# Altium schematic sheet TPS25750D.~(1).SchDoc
size A2; Date: Not shown in title block; ApprovedBy: Not shown in title block; CheckedBy: Not shown in title block; Author: Not shown in title block; CompanyName: Not shown in title block; Engineer: Not shown in title block; Organization: Not shown in title block; Address1: Not shown in title block; Address2: Not shown in title block; Address3: Not shown in title block; Address4: Not shown in title block; DocumentNumber: 2; Revision: Use project parameter SCH_Rev; SheetNumber: 2; SheetTotal: 3; PageSetup: Record=PageOptions¦CenterHorizontal=True¦CenterVertical=True¦PrintScale=1.00¦XCorrection=1.00¦YCorrection=1.00¦PrintKind=0¦BorderSize=5000000¦LeftOffset=0¦BottomOffset=0¦Orientation=2¦PaperLength=1000¦PaperWidth=1000¦Scale=100¦PaperSource=15¦PrintQuality=600¦MediaType=1¦DitherType=10¦PaperKind=Letter¦PrintScaleMode=1
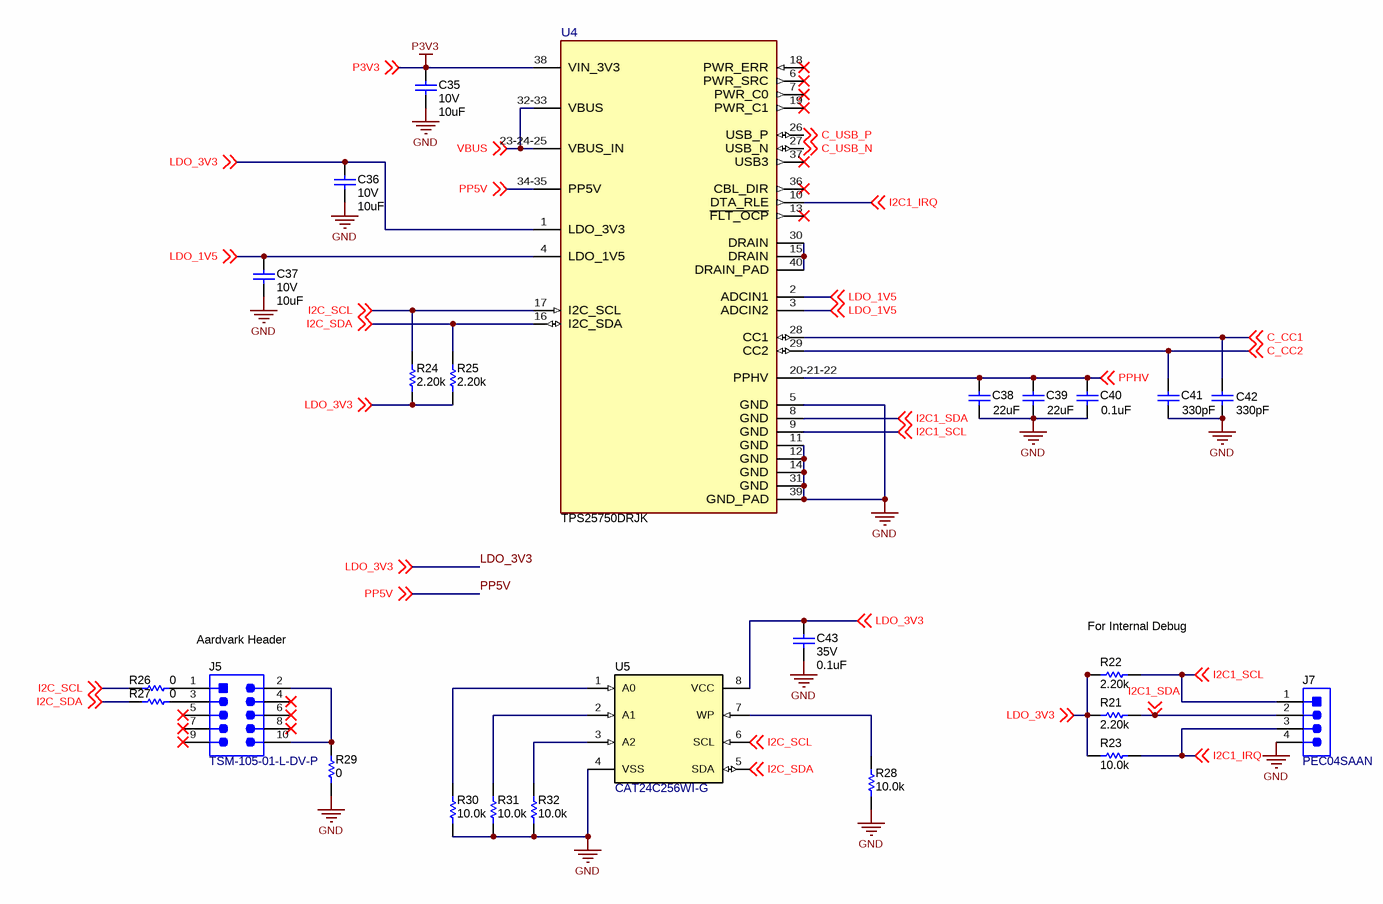
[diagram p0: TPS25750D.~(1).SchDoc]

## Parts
C35  VDC_V: 10V  ValueDisplayed: 10uF  [0402_070]  (hidden comment: CL05A106MP5NUNC)
C36  VDC_V: 10V  ValueDisplayed: 10uF  [0402_070]  (hidden comment: CL05A106MP5NUNC)
C37  VDC_V: 10V  ValueDisplayed: 10uF  [0402_070]  (hidden comment: CL05A106MP5NUNC)
C38  ValueDisplayed: 22uF  [0805_HV]  (hidden comment: C2012X5R1V226M125AC)
C39  ValueDisplayed: 22uF  [0805_HV]  (hidden comment: C2012X5R1V226M125AC)
C40  ValueDisplayed: 0.1uF  [0402]  (hidden comment: GMK105BJ104KV-F)
C41  ValueDisplayed: 330pF  [0201_033]  (hidden comment: GRM033R71H331KA12D)
C42  ValueDisplayed: 330pF  [0201_033]  (hidden comment: GRM033R71H331KA12D)
C43  VDC_V: 35V  ValueDisplayed: 0.1uF  [0402]  (hidden comment: GMK105BJ104KV-F)
J5  TSM-105-01-L-DV-P  [Samtec_TSM-105-01-x-DV]
J7  PEC04SAAN  [SULLINS_PEC04SAAN]
R21  ValueDisplayed: 2.20k  [0201]  (hidden comment: CRCW02012K20FKED)
R22  ValueDisplayed: 2.20k  [0201]  (hidden comment: CRCW02012K20FKED)
R23  ValueDisplayed: 10.0k  [0201]  (hidden comment: CRCW020110K0FKED)
R24  ValueDisplayed: 2.20k  [0201]  (hidden comment: CRCW02012K20FKED)
R25  ValueDisplayed: 2.20k  [0201]  (hidden comment: CRCW02012K20FKED)
R26  ValueDisplayed: 0  [0201]  (hidden comment: CRCW02010000Z0ED)
R27  ValueDisplayed: 0  [0201]  (hidden comment: CRCW02010000Z0ED)
R28  ValueDisplayed: 10.0k  [0201]  (hidden comment: CRCW020110K0FKED)
R29  ValueDisplayed: 0  [0201]  (hidden comment: CRCW02010000Z0ED)
R30  ValueDisplayed: 10.0k  [0201]  (hidden comment: CRCW020110K0FKED)
R31  ValueDisplayed: 10.0k  [0201]  (hidden comment: CRCW020110K0FKED)
R32  ValueDisplayed: 10.0k  [0201]  (hidden comment: CRCW020110K0FKED)
U4  TPS25750DRJK  [RJK0038B-C01-MFG]
U5  CAT24C256WI-G  [SOIC-8]

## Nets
GND: C35.2 C36.2 C37.2 C38.2 C39.2 C40.2 C41.2 C42.2 C43.2 J7.4 R28.1 R29.1 R30.1 R31.1 R32.1 U4.5(GND) U4.11(GND) U4.12(GND) U4.14(GND) U4.31(GND) U4.39(GND_PAD) U5.4(VSS)
P3V3: C35.1 U4.38(VIN_3V3) ; off-sheet P3V3
C_CC1: C42.1 U4.28(CC1) ; off-sheet C_CC1
C_CC2: C41.1 U4.29(CC2) ; off-sheet C_CC2
C_USB_N: U4.27(USB_N) ; off-sheet C_USB_N
C_USB_P: U4.26(USB_P) ; off-sheet C_USB_P
I2C1_IRQ: J7.3 R23.1 U4.10(DTA_RLE) ; off-sheet I2C1_IRQ
I2C1_SCL: J7.1 R22.1 U4.9(GND) ; off-sheet I2C1_SCL
I2C1_SDA: J7.2 R21.1 U4.8(GND) ; off-sheet I2C1_SDA
I2C_SCL: R24.2 R26.1 U4.17(I2C_SCL) U5.6(SCL) ; off-sheet I2C_SCL
I2C_SDA: R25.2 R27.1 U4.16(I2C_SDA) U5.5(SDA) ; off-sheet I2C_SDA
LDO_1V5: C37.1 U4.2(ADCIN1) U4.3(ADCIN2) U4.4(LDO_1V5) ; off-sheet LDO_1V5
LDO_3V3: C36.1 C43.1 R21.2 R22.2 R23.2 R24.1 R25.1 U4.1(LDO_3V3) U5.8(VCC) ; off-sheet LDO_3V3
PP5V: U4.34-35(PP5V) ; off-sheet PP5V
PPHV: C38.1 C39.1 C40.1 U4.20-21-22(PPHV) ; off-sheet PPHV
VBUS: U4.23-24-25(VBUS_IN) U4.32-33(VBUS) ; off-sheet VBUS
NetJ5_1: J5.1 R26.2
NetJ5_2: J5.2 J5.10 R29.2
NetJ5_3: J5.3 R27.2
NetR28_2: R28.2 U5.7(WP)
NetR30_2: R30.2 U5.1(A0)
NetR31_2: R31.2 U5.2(A1)
NetR32_2: R32.2 U5.3(A2)
NetU4_15: U4.15(DRAIN) U4.30(DRAIN) U4.40(DRAIN_PAD)

Not connected (* = marked no-connect by the designer): J5 4* 5* 6* 7* 8* 9*; U4 6(PWR_SRC)* 7(PWR_C0)* 13(~{FLT_OCP})* 18(PWR_ERR)* 19(PWR_C1)* 36(CBL_DIR)* 37(USB3)*

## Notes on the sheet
- Aardvark Header
- (near R22) For Internal Debug

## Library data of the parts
C35-C37 = CMP-0006339-4: CAP, CERM, 10 uF, 10 V, +/- 20%, X5R, 0402; Manufacturer: Samsung Electro-Mechanics; TaMin_C: -55°C; Polarized: N; SizeAreaWB_mm2: 3; Value1: Unknown; U/M: EA; Value: 10uF; TaMax_C: 85°C; SizeZ_mm: 0.6; SizeX_mm: 1; SizeY_mm: 0.5; Cap_Case: 0402; Cap_F: 10µF; AEC Category: Q200
C38 C39 = CMP-0007844-2: CAP, CERM, 22 uF, 35 V, +/- 20%, X5R, 0805; Manufacturer: TDK; TaMin_C: -55°C; ESR_ohm: 2.05m; Polarized: N; SizeAreaWB_mm2: 6.75; Value1: 0.00205 ohm; U/M: EA; Value: 22uF; TaMax_C: 85°C; SizeZ_mm: 1.45; SizeX_mm: 2; SizeY_mm: 1.25; Cap_Case: 0805; Value2: 35V; SizeArea_mm2: 2.5; Cap_F: 22µF; IRMS_A: 4.55587A; AEC Category: Q200
C40 = CMP-0006370-2: CAP, CERM, 0.1 uF, 35 V, +/- 10%, X5R, 0402; Manufacturer: Taiyo Yuden; TaMin_C: -55°C; Polarized: N; SizeAreaWB_mm2: 3; Value1: Unknown; U/M: EA; Value: 0.1uF; TaMax_C: 85°C; SizeZ_mm: 0.6; SizeX_mm: 1; SizeY_mm: 0.5; Value2: 35V; Cap_F: 100nF; AEC Category: Q200
C41 C42 = CMP-0009779-2: CAP, CERM, 330 pF, 50 V, +/- 10%, X7R, 0201; Manufacturer: MuRata; TaMin_C: -55°C; Polarized: N; SizeAreaWB_mm2: 2.08; Value1: Unknown; U/M: EA; Value: 330pF; TaMax_C: 125°C; SizeZ_mm: 0.33; SizeX_mm: 0.6; SizeY_mm: 0.3; Cap_Case: 0201; Value2: 50V; SizeArea_mm2: 0.18; AEC Category: Q200
C43 = CMP-0006370-2: CAP, CERM, 0.1 uF, 35 V, +/- 10%, X5R, 0402; Manufacturer: Taiyo Yuden; TaMin_C: -55°C; Polarized: N; SizeAreaWB_mm2: 3; Value1: Unknown; U/M: EA; Value: 0.1uF; TaMax_C: 85°C; SizeZ_mm: 0.6; SizeX_mm: 1; SizeY_mm: 0.5; Cap_F: 100nF; AEC Category: Q200
J5 = CMP-0055598-2: Header, 2.54mm, 5x2, Gold, SMT; Manufacturer: Samtec; Current_A: 5.4A; Green_Lifecycle: Active; Shrouded: N; Gender: Male; Cert_CSA: Y; Green_REACh: Passed; Voltage_V: 475V; Row_Count: 2; RowSpacing_mm: 2.54
J7 = CMP-0054562-1: Header, 100mil, 4x1, Tin, TH; Manufacturer: Sullins Connector Solutions; CNHeader: TRUE; Current_A: 3A; Green_Lifecycle: Not Set; Shrouded: N; Gender: Male; Green_REACh: Incomplete; Voltage_V: 1.8kV; Row_Count: 1; Pitch_mm: 2.54; CT: FALSE; Cert_UL: Y
R21 R22 R24 R25 = CMP-0027272-3: RES, 2.20 k, 1%, 0.05 W, 0201; Manufacturer: Vishay-Dale; Power_W: 50mW; TempCo: 100 ppm/C; Value_Code: 2k20; Value: 2.20k; Res_ohm: 2.2k; SizeX_mm: 0.6; SizeY_mm: 0.3; SizeZ_mm: 0.26; Value2: 0.05W; SizeArea_mm2: 0.18; AEC Qualified: N; VDC_V: 30V; AEC Category: Q200
R23 R28 R30-R32 = CMP-0027262-3: RES, 10.0 k, 1%, 0.05 W, 0201; Manufacturer: Vishay-Dale; Power_W: 50mW; TempCo: 100 ppm/C; Value_Code: 10k0; Value: 10.0k; EIA_Code: E96; Res_ohm: 10k; SizeX_mm: 0.6; SizeY_mm: 0.3; SizeZ_mm: 0.26; Value2: 0.05W; SizeArea_mm2: 0.18; AEC Qualified: N; VDC_V: 30V; AEC Category: Q200
R26 R27 R29 = CMP-0027008-4: RES, 0, 5%, 0.05 W, 0201; Manufacturer: Vishay-Dale; Power_W: 50mW; TempCo: ppm/C; Value_Code: 0000; Value: 0; EIA_Code: E24; SizeX_mm: 0.6; SizeY_mm: 0.3; SizeZ_mm: 0.26; Value2: 0.05W; SizeArea_mm2: 0.18; AEC Qualified: N; AEC Category: Q200
U4 = CMP-0090338-2: USB Type-C and USB PD Controller with Integrated Power Switches Optimized for Power Applications; Manufacturer: Texas Instruments; Usb Standard: USB 3.0; TJmax_C: +175°C; AEC Category: Q200; CompType: IC; Number Of Ports: 1; TaMax_C: +105°C; TaMin_C: -40°C; Standoff Height: 0mm; AEC Qualified: No; Max Supply Voltage: 22V; SizeZ_mm: 0.8mm; Min Supply Voltage: 3V
U5 = CMP-0005314-2: 256 kb I2C CMOS Serial EEPROM, SOIC-8; Manufacturer: ON Semiconductor; SizeAreaWB_mm2: 55.131; SizeZ_mm: 1.75; SizeX_mm: 5.99; SizeY_mm: 4.9; SizeArea_mm2: 29.351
